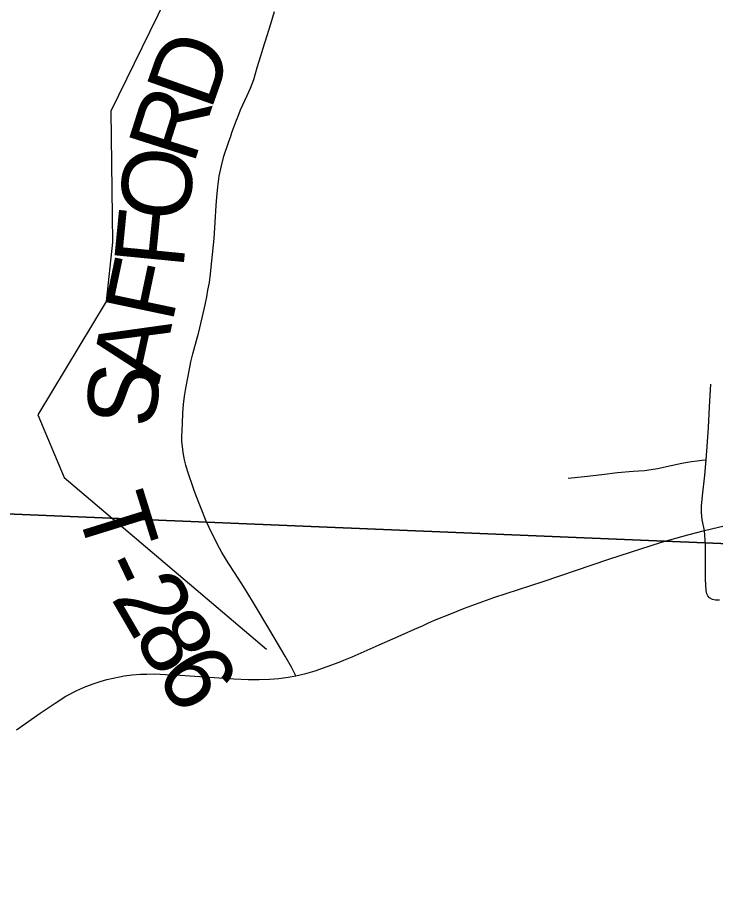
# Model space of a CAD drawing. Extents: x 0 to 34, y 0 to 22.
# Drawn here: x 26.889 to 27.458, y 18.718 to 19.422 of the extents above; entities that cross this region are included whole.
import ezdxf

# ---------------------------------------------------------------- set-up
doc = ezdxf.new("R2010")
doc.units = 0
for name, color, linetype in [('GM_X_Minor_River', 7, 'Continuous'), ('GM_X_Section', 7, 'Continuous'), ('GM_X_State_Route', 7, 'Continuous'), ('GM_X_Township_Road', 7, 'Continuous'), ('GM_X_Township_Road_Text', 7, 'Continuous')]:
    doc.layers.add(name, color=color, linetype=linetype)

msp = doc.modelspace()

# ---------------------------------------------------------------- linework, layer by layer
at = {"layer": 'GM_X_Minor_River'}
msp.add_lwpolyline([(27.00981, 19.43639), (26.96508, 19.34492), (26.96649, 19.23829), (26.96143, 19.18968), (26.9057, 19.09734), (26.92726, 19.0463), (27.09196, 18.90621)], dxfattribs=at)
at = {"layer": 'GM_X_Section'}
for points in [[(27.66887, 20.01117), (27.60613, 18.98645), (26.56518, 19.02981), (26.57566, 19.21247), (26.60083, 19.63555), (26.62526, 20.05603)], [(26.56518, 19.02981), (27.60613, 18.98645), (27.59412, 18.77048), (27.5794, 18.52138), (27.56056, 18.20429), (27.54604, 17.95833), (26.49486, 18.00355), (26.55102, 18.79468)]]:
    msp.add_lwpolyline(points, close=True, dxfattribs=at)
at = {"layer": 'GM_X_State_Route'}
for points in [[(27.15503, 18.8973), (27.16173, 18.90006), (27.18384, 18.90992), (27.19498, 18.91479), (27.20428, 18.91884), (27.21258, 18.92254), (27.21904, 18.92541), (27.22415, 18.92765), (27.23039, 18.93038), (27.24134, 18.9348), (27.2533, 18.93963), (27.27714, 18.94827), (27.31736, 18.96152), (27.37096, 18.97958), (27.41392, 18.99345), (27.43524, 18.99942), (27.44904, 19.00306), (27.49237, 19.01324)], [(26.88818, 18.84045), (26.90759, 18.85407), (26.91973, 18.86221), (26.92848, 18.86789), (26.93739, 18.8725), (26.94467, 18.8758), (26.95165, 18.87836), (26.95658, 18.88002), (26.96177, 18.88141), (26.96715, 18.88265), (26.97229, 18.88369), (26.97611, 18.88439), (26.98253, 18.88523), (26.98929, 18.88582), (26.99437, 18.88601), (27.00097, 18.88607), (27.00969, 18.88572), (27.0216, 18.88512), (27.06544, 18.88221), (27.07704, 18.88162), (27.08615, 18.88152), (27.09436, 18.88182), (27.10216, 18.88242), (27.10962, 18.88337), (27.116, 18.88457), (27.12418, 18.88652), (27.13179, 18.88872), (27.1415, 18.89203), (27.1512, 18.89573), (27.15503, 18.8973)]]:
    msp.add_lwpolyline(points, dxfattribs=at)
at = {"layer": 'GM_X_Township_Road'}
for points in [[(27.03576, 19.16103), (27.0365, 19.16381), (27.03965, 19.17636), (27.04203, 19.18716), (27.04326, 19.19355), (27.04431, 19.19905), (27.04547, 19.20535), (27.0465, 19.21247), (27.04742, 19.22289), (27.04923, 19.24114), (27.05022, 19.25455), (27.05099, 19.268), (27.05142, 19.27476), (27.05226, 19.28338), (27.05354, 19.29198), (27.05529, 19.3005), (27.05732, 19.30829), (27.06099, 19.31942), (27.06284, 19.32468), (27.06387, 19.32761), (27.06515, 19.3311), (27.06598, 19.33344), (27.06704, 19.33636), (27.06883, 19.34099), (27.07093, 19.34615), (27.07621, 19.35781), (27.07885, 19.36365), (27.0816, 19.37092), (27.08314, 19.37566), (27.08445, 19.38076), (27.08734, 19.39025), (27.08908, 19.39552), (27.09251, 19.40679), (27.09553, 19.41624), (27.09863, 19.42634)], [(27.07594, 18.95315), (27.07333, 18.95749), (27.0666, 18.96785), (27.06082, 18.97666), (27.05565, 18.98511), (27.05179, 18.99218), (27.04522, 19.00553), (27.04295, 19.01063), (27.0387, 19.02095), (27.03472, 19.03137), (27.03283, 19.03661), (27.02751, 19.05175), (27.0262, 19.05631), (27.02513, 19.0606), (27.02399, 19.06671), (27.02343, 19.07165), (27.02311, 19.07559), (27.02311, 19.07944), (27.0235, 19.09027), (27.02388, 19.09872), (27.02441, 19.10576), (27.02527, 19.11253), (27.02629, 19.11925), (27.02805, 19.129), (27.03045, 19.14052), (27.03203, 19.14713), (27.03576, 19.16103)], [(27.44904, 19.00306), (27.44713, 19.01185), (27.44671, 19.01467), (27.44649, 19.01759), (27.44647, 19.02028), (27.44656, 19.02294), (27.44727, 19.03137), (27.44927, 19.04816), (27.45036, 19.06055), (27.45134, 19.07537), (27.45213, 19.08702), (27.45309, 19.10378), (27.45401, 19.12229)], [(27.33784, 19.04566), (27.35125, 19.04719), (27.36517, 19.04883), (27.37808, 19.05027), (27.39091, 19.05131), (27.40007, 19.05208), (27.40538, 19.05274), (27.41059, 19.05369), (27.4219, 19.05617), (27.42552, 19.05697), (27.42904, 19.05771), (27.43358, 19.05857), (27.43842, 19.05932), (27.44287, 19.05989), (27.44685, 19.06037), (27.45036, 19.06055)], [(27.46129, 18.94628), (27.458, 18.9462), (27.45537, 18.94677), (27.453, 18.94809), (27.45165, 18.94965), (27.45079, 18.95151), (27.45023, 18.95413), (27.44983, 18.96337), (27.44964, 18.97401), (27.4498, 18.99116), (27.44904, 19.00306)], [(27.116, 18.88457), (27.11227, 18.89152), (27.10733, 18.90064), (27.09486, 18.92185), (27.08221, 18.94273), (27.07594, 18.95315)]]:
    msp.add_lwpolyline(points, dxfattribs=at)

# ---------------------------------------------------------------- texts
at = {"layer": 'GM_X_Township_Road_Text'}
for s, rotation, p in [('D', 70.5743, (27.04655, 19.34456)), ('R', 72.35004, (27.03255, 19.30053)), ('O', 83.91967, (27.02788, 19.25378)), ('F', 84.42024, (27.02417, 19.21576)), ('F', 78.1009, (27.01522, 19.17149)), ('A', 77.65057, (27.00443, 19.12217)), ('S', 84.27947, (27.00088, 19.08574)), ('T', 287.28833, (26.93651, 19.02237)), ('-', 295.51513, (26.95238, 18.97352)), ('2', 300.17874, (26.96479, 18.948)), ('8', 300.84669, (26.98275, 18.91712)), ('6', 301.07143, (27.00082, 18.88687))]:
    msp.add_text(s, height=0.05682, rotation=rotation, dxfattribs=at).set_placement(p)

doc.saveas('drawing.dxf')
